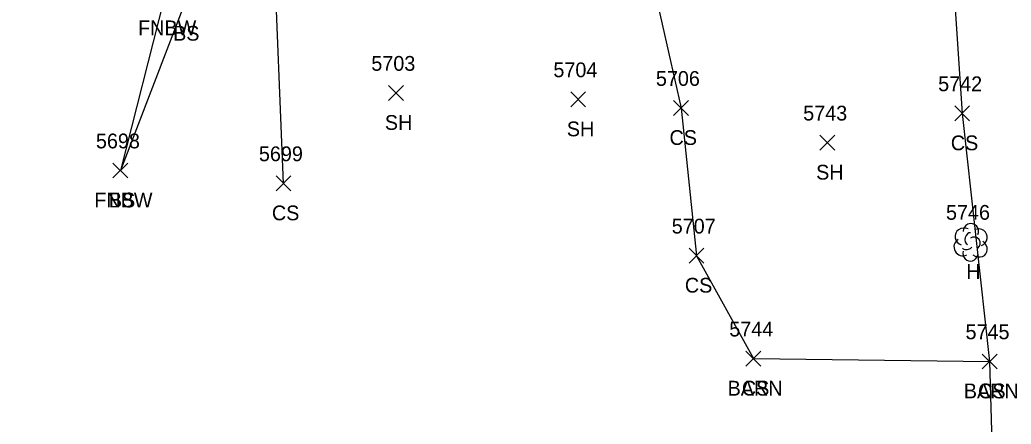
# Model space of a CAD drawing. Extents: x 1443912 to 1445411, y 621446 to 623693.
# Drawn here: x 1444474.8 to 1444608.9, y 622412.7 to 622467.5 of the extents above; entities that cross this region are included whole.
import ezdxf

# ---------------------------------------------------------------- set-up
doc = ezdxf.new("R2010")
doc.units = 0
for name, color, linetype in [('L_A', 7, 'Continuous'), ('L_I', 7, 'Continuous'), ('L_TIC', 7, 'Continuous'), ('LBC', 7, 'Continuous'), ('LELB', 7, 'Continuous'), ('LFNC', 7, 'Continuous'), ('LTD', 7, 'Continuous')]:
    doc.layers.add(name, color=color, linetype=linetype)

msp = doc.modelspace()

# ---------------------------------------------------------------- linework, layer by layer
at = {"layer": 'L_TIC'}
for points in [[(1444524.69, 622456.59), (1444526.69, 622458.59)], [(1444526.69, 622456.59), (1444524.69, 622458.59)], [(1444549.32, 622455.72), (1444551.32, 622457.72)], [(1444551.32, 622455.72), (1444549.32, 622457.72)], [(1444563.25, 622454.55), (1444565.25, 622456.55)], [(1444565.25, 622454.55), (1444563.25, 622456.55)], [(1444601.3, 622453.83), (1444603.3, 622455.83)], [(1444603.3, 622453.83), (1444601.3, 622455.83)], [(1444583.04, 622449.86), (1444585.04, 622451.86)], [(1444585.04, 622449.86), (1444583.04, 622451.86)], [(1444487.4, 622446.09), (1444489.4, 622448.09)], [(1444489.4, 622446.09), (1444487.4, 622448.09)], [(1444487.4, 622446.09), (1444489.4, 622448.09)], [(1444489.4, 622446.09), (1444487.4, 622448.09)], [(1444509.46, 622444.35), (1444511.46, 622446.35)], [(1444511.46, 622444.35), (1444509.46, 622446.35)], [(1444565.33, 622434.56), (1444567.33, 622436.56)], [(1444567.33, 622434.56), (1444565.33, 622436.56)], [(1444573.04, 622420.62), (1444575.04, 622422.62)], [(1444575.04, 622420.62), (1444573.04, 622422.62)], [(1444573.04, 622420.62), (1444575.04, 622422.62)], [(1444575.04, 622420.62), (1444573.04, 622422.62)], [(1444605, 622420.25), (1444607, 622422.25)], [(1444607, 622420.25), (1444605, 622422.25)], [(1444605, 622420.25), (1444607, 622422.25)], [(1444607, 622420.25), (1444605, 622422.25)]]:
    msp.add_lwpolyline(points, dxfattribs=at)
at = {"layer": 'LBC'}
msp.add_lwpolyline([(1444574.04, 622421.62), (1444606, 622421.25), (1444606.42, 622405.63), (1444584.48, 622405.65)], dxfattribs=at)
at = {"layer": 'LELB'}
for points in [[(1444418.48, 622504.7), (1444424.76, 622515.07), (1444427.19, 622516.9), (1444460.05, 622519.54), (1444495.46, 622522.51), (1444512.1, 622522.4), (1444505.48, 622498.66), (1444497.09, 622469.67), (1444488.4, 622447.09)], [(1444600.33, 622483.81), (1444602.3, 622454.83), (1444606, 622421.25)], [(1444510.46, 622445.35), (1444509.17, 622477.69), (1444534.12, 622472.61), (1444547.95, 622474.84), (1444559.97, 622474.52), (1444564.25, 622455.55), (1444566.33, 622435.56), (1444574.04, 622421.62)]]:
    msp.add_lwpolyline(points, dxfattribs=at)
at = {"layer": 'LFNC'}
msp.add_lwpolyline([(1444502.22, 622503.57), (1444501.78, 622498.51), (1444494.32, 622470.4), (1444488.4, 622447.09)], dxfattribs=at)
at = {"layer": 'LTD'}
msp.add_line((1444603.41, 622437.42), (1444603.41, 622437.42), dxfattribs=at)
msp.add_line((1444603.41, 622437.42), (1444603.41, 622437.42), dxfattribs=at)
msp.add_arc((1444603.46, 622438.85), 1.05, 335.5272, 180.9563, dxfattribs=at)
for centre, major_axis, ratio, start_param, end_param in [((1444602.62, 622438.09), (1.21, -0.51), 0.895232, 1.570796, 4.712389), ((1444603.2, 622437.88), (-0.208, -0.792), 0.645439, 3.141593, 6.283185), ((1444603.91, 622437.25), (-0.5, 0.667), 0.989748, 3.141593, 6.283185), ((1444604.45, 622438), (-1.14, -0.48), 0.949671, 1.570796, 4.712389), ((1444602.33, 622436.71), (0.58, -1.04), 0.959034, 3.141593, 6.283185), ((1444604.41, 622436.59), (-1.09, 0.79), 0.841452, 1.570796, 4.712389), ((1444603.41, 622435.92), (0.26, 1.06), 0.942809, 1.570796, 4.712389), ((1444602.95, 622436.67), (-0.625, -0.083), 0.423636, 0, 3.141593)]:
    msp.add_ellipse(centre, major_axis=major_axis, ratio=ratio, start_param=start_param, end_param=end_param, dxfattribs=at)

# ---------------------------------------------------------------- texts
at = {"layer": 'L_A'}
for s, p in [('FNBW', (1444490.79, 622465.4)), ('BS', (1444495.53, 622464.67)), ('SH', (1444524.18, 622452.59)), ('SH', (1444548.8, 622451.72)), ('CS', (1444562.69, 622450.55)), ('CS', (1444600.75, 622449.83)), ('SH', (1444582.53, 622445.86)), ('FNBW', (1444484.87, 622442.09)), ('BS', (1444486.84, 622442.09)), ('CS', (1444508.9, 622440.35)), ('H', (1444602.84, 622432.42)), ('CS', (1444564.77, 622430.56)), ('BARN', (1444570.55, 622416.62)), ('CS', (1444572.48, 622416.62)), ('BARN', (1444602.51, 622416.25)), ('CS', (1444604.44, 622416.25))]:
    msp.add_text(s, height=2, dxfattribs=at).set_placement(p)
at = {"layer": 'L_I'}
for s, p in [('5703', (1444522.35, 622460.59)), ('5704', (1444546.98, 622459.72)), ('5706', (1444560.85, 622458.55)), ('5742', (1444599.04, 622457.83)), ('5743', (1444580.78, 622453.86)), ('5698', (1444485.09, 622450.09)), ('5698', (1444485.09, 622450.09)), ('5699', (1444507.14, 622448.35)), ('5746', (1444600.1, 622440.42)), ('5707', (1444562.99, 622438.56)), ('5744', (1444570.78, 622424.62)), ('5744', (1444570.78, 622424.62)), ('5745', (1444602.74, 622424.25)), ('5745', (1444602.74, 622424.25))]:
    msp.add_text(s, height=2, dxfattribs=at).set_placement(p)

doc.saveas('drawing.dxf')
